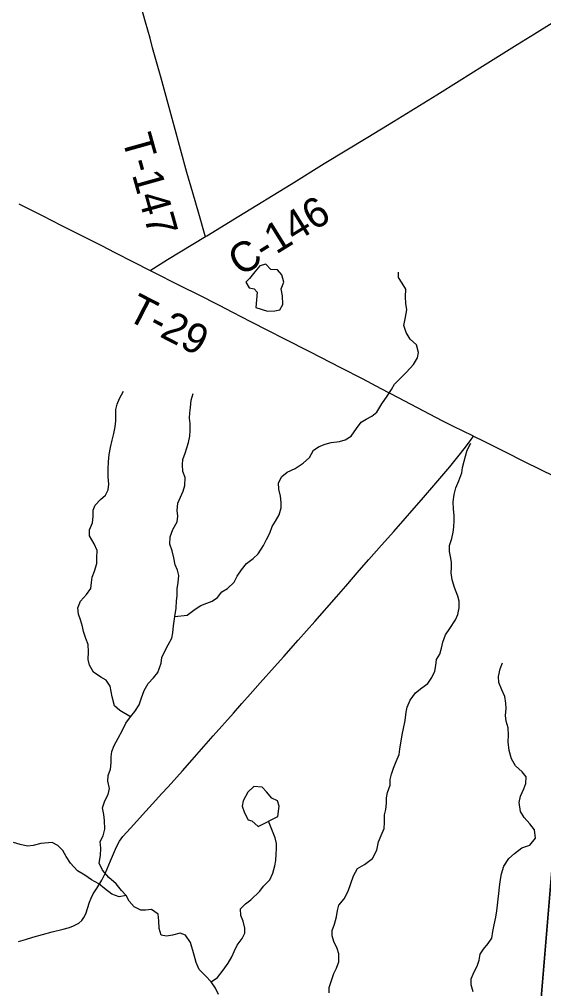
# Model space of a CAD drawing. Extents: x 0 to 1101, y 0 to 440.
# Drawn here: x 846.711 to 847.707, y 379.047 to 380.89 of the extents above; entities that cross this region are included whole.
import ezdxf

# ---------------------------------------------------------------- set-up
doc = ezdxf.new("R2010")
doc.units = 0
for name, color, linetype in [('GM_X_County_Road', 7, 'Continuous'), ('GM_X_County_Road_Text', 7, 'Continuous'), ('GM_X_Minor_Lake', 7, 'Continuous'), ('GM_X_Minor_River', 7, 'Continuous'), ('GM_X_Township_Road', 7, 'Continuous'), ('GM_X_Township_Road_Text', 7, 'Continuous')]:
    doc.layers.add(name, color=color, linetype=linetype)

msp = doc.modelspace()

# ---------------------------------------------------------------- linework, layer by layer
at = {"layer": 'GM_X_County_Road'}
for points in [[(847.5335, 377.0456), (847.6089, 377.9284), (847.6897, 378.8763), (847.7828, 379.9871), (847.8653, 380.9722), (847.896, 381.3391), (846.8323, 381.427), (846.7789, 381.4314), (846.7617, 381.4329), (846.7534, 381.4335), (845.8327, 381.5116), (845.7218, 381.5239), (845.7047, 381.5258), (845.3492, 381.569), (845.0655, 381.6042), (845.008, 381.6114), (844.8229, 381.6343), (844.8107, 381.6358), (844.7738, 381.6404), (844.7118, 381.648), (844.0658, 381.7282)], [(846.9593, 380.4123), (846.9919, 380.4329), (847.0643, 380.4767), (847.0668, 380.4783), (847.1277, 380.5156), (847.2275, 380.5763), (847.2903, 380.6153), (847.3731, 380.6657), (847.4219, 380.6955), (847.5045, 380.7461), (847.5467, 380.7725), (847.5913, 380.8007), (847.6571, 380.842), (847.6898, 380.8623), (847.7238, 380.8828), (847.7671, 380.9084), (847.7921, 380.9236), (847.8525, 380.9605), (847.8635, 380.9676), (847.867, 380.9703), (847.8692, 380.9721)], [(846.7098, 380.5388), (846.7552, 380.5158), (846.7896, 380.4984), (846.8323, 380.4768), (846.8678, 380.459), (846.891, 380.4471), (846.928, 380.428), (846.9593, 380.4123)]]:
    msp.add_lwpolyline(points, dxfattribs=at)
msp.add_lwpolyline([(850.9258, 375.8797), (850.9258, 381.1617), (850.8488, 381.1661), (850.84, 381.1666), (850.8316, 381.167), (850.794, 381.1689), (850.7928, 381.169), (849.9699, 381.2155), (849.9584, 381.2161), (849.5879, 381.237), (848.2076, 381.3203), (847.9626, 381.3347), (847.896, 381.3391), (847.8653, 380.9722), (847.7828, 379.9871), (847.6897, 378.8763), (847.6089, 377.9284), (847.5335, 377.0456), (847.5303, 377.0082), (847.4662, 376.2566), (847.7946, 376.221), (849.0627, 376.0925), (849.9034, 375.9956), (850.1463, 375.9688)], close=True, dxfattribs=at)
at = {"layer": 'GM_X_Minor_Lake'}
for points in [[(847.1601, 380.3417), (847.1824, 380.3349), (847.196, 380.3355), (847.2055, 380.3376), (847.2117, 380.3474), (847.2108, 380.3641), (847.2084, 380.3774), (847.2131, 380.3899), (847.2099, 380.404), (847.2013, 380.4132), (847.1888, 380.4141), (847.1791, 380.4241), (847.1677, 380.4213), (847.158, 380.4096), (847.148, 380.3969), (847.1414, 380.3897), (847.1474, 380.379), (847.1568, 380.3774), (847.1624, 380.3709)], [(847.1624, 380.3709), (847.1601, 380.3417)], [(847.2018, 379.3739), (847.2044, 379.3936), (847.2011, 379.4035), (847.1909, 379.4086), (847.1805, 379.4208), (847.1723, 379.4297), (847.1564, 379.4307), (847.1452, 379.4202), (847.1363, 379.4036), (847.1342, 379.3938), (847.1386, 379.3808), (847.1456, 379.3678), (847.1528, 379.3655), (847.1644, 379.3547)], [(847.1644, 379.3547), (847.2018, 379.3739)]]:
    msp.add_lwpolyline(points, dxfattribs=at)
at = {"layer": 'GM_X_Minor_River'}
for points in [[(847.0063, 379.7542), (847.0295, 379.7569), (847.0448, 379.768), (847.0559, 379.7751), (847.0673, 379.7795), (847.0772, 379.7831), (847.0872, 379.7906), (847.0953, 379.8011), (847.1064, 379.8074), (847.1187, 379.8197), (847.1245, 379.8307), (847.133, 379.8431), (847.1427, 379.8551), (847.1553, 379.8647), (847.1649, 379.8737), (847.1746, 379.8891), (847.1805, 379.9008), (847.1867, 379.9129), (847.191, 379.9253), (847.1976, 379.9355), (847.2046, 379.9475), (847.2086, 379.9608), (847.2084, 379.971), (847.207, 379.9828), (847.2042, 379.9965), (847.2032, 380.0086), (847.2094, 380.0207), (847.2198, 380.0289), (847.235, 380.0355), (847.25, 380.0459), (847.2619, 380.0568), (847.27, 380.0707), (847.2803, 380.0777), (847.2922, 380.0821), (847.3036, 380.085), (847.3191, 380.0871), (847.3298, 380.09), (847.3413, 380.0974), (847.3517, 380.112), (847.3606, 380.1237), (847.3701, 380.1296), (847.3805, 380.1352), (847.39, 380.143), (847.3997, 380.1584), (847.4098, 380.1734), (847.4183, 380.1858), (847.4241, 380.196), (847.4364, 380.2084), (847.4468, 380.2188), (847.4599, 380.2331), (847.4677, 380.2462), (847.4693, 380.2565), (847.4654, 380.2709), (847.4538, 380.2817), (847.446, 380.2944), (847.4416, 380.3073), (847.4445, 380.3236), (847.4473, 380.3372), (847.4456, 380.3494), (847.445, 380.3619), (847.4452, 380.3767), (847.4382, 380.3882), (847.4315, 380.3986), (847.4313, 380.4088)], [(846.9221, 379.5637), (846.9018, 379.5754), (846.8913, 379.5843), (846.8867, 379.6014), (846.8853, 379.6117), (846.8832, 379.6216), (846.8754, 379.6335), (846.8656, 379.6389), (846.8513, 379.6482), (846.8436, 379.6616), (846.8411, 379.6726), (846.842, 379.687), (846.8415, 379.7007), (846.8367, 379.7125), (846.8323, 379.7259), (846.8309, 379.7354), (846.827, 379.7476), (846.8229, 379.7586), (846.8216, 379.7708), (846.8271, 379.7836), (846.8382, 379.796), (846.8464, 379.8076), (846.848, 379.8186), (846.8493, 379.8292), (846.8533, 379.8406), (846.8577, 379.8553), (846.8578, 379.8659), (846.8584, 379.8796), (846.8529, 379.8925), (846.8436, 379.9079), (846.8438, 379.9192), (846.8496, 379.9324), (846.8506, 379.9442), (846.8511, 379.9563), (846.855, 379.9661), (846.8647, 379.9766), (846.8743, 379.9852), (846.8797, 379.995), (846.8806, 380.006), (846.8797, 380.0197), (846.8795, 380.0341), (846.8801, 380.0485), (846.8814, 380.0621), (846.8839, 380.0754), (846.8871, 380.0894), (846.8899, 380.1019), (846.8924, 380.1151), (846.8941, 380.1261), (846.8938, 380.1363), (846.894, 380.1481), (846.8964, 380.1579), (846.9011, 380.1689), (846.9085, 380.1824)], [(847.0135, 379.8322), (847.0114, 379.8425), (847.0066, 379.8528), (847.0045, 379.8661), (847.0013, 379.8791), (846.9969, 379.892), (846.9971, 379.9057), (847.0026, 379.9196), (847.0104, 379.934), (847.0117, 379.9449), (847.0107, 379.956), (847.0116, 379.9696), (847.0167, 379.9813), (847.0222, 379.9926), (847.0254, 380.0036), (847.026, 380.0184), (847.0212, 380.0298), (847.0206, 380.0427), (847.0215, 380.0529), (847.0255, 380.0647), (847.029, 380.0752), (847.0322, 380.0851), (847.0346, 380.0972), (847.0355, 380.107), (847.0354, 380.1211), (847.034, 380.1313), (847.0349, 380.1412), (847.0358, 380.1518), (847.0375, 380.1654), (847.0411, 380.1783)], [(847.5534, 380.0375), (847.5562, 380.0496), (847.559, 380.0594), (847.5618, 380.0704), (847.5689, 380.0839)], [(847.2998, 379.039), (847.2999, 379.0488), (847.3039, 379.0621), (847.3082, 379.0753), (847.3137, 379.0855), (847.3177, 379.0979), (847.3179, 379.1127), (847.315, 379.123), (847.3087, 379.136), (847.3051, 379.147), (847.3056, 379.1573), (847.3096, 379.169), (847.3136, 379.183), (847.3153, 379.1955), (847.3181, 379.2053), (847.3281, 379.2177), (847.3355, 379.232), (847.341, 379.2463), (847.3457, 379.261), (847.3535, 379.275), (847.3669, 379.2824), (847.3818, 379.2939), (847.39, 379.3101), (847.3933, 379.326), (847.3984, 379.3381), (847.4039, 379.3509), (847.4048, 379.3627), (847.4046, 379.3771), (847.4074, 379.3873), (847.4083, 379.3994), (847.4085, 379.4093), (847.4105, 379.4195), (847.4157, 379.4335), (847.4158, 379.4441), (847.4178, 379.4547), (847.4222, 379.4656), (847.4269, 379.4784), (847.4324, 379.492), (847.4341, 379.5022), (847.4382, 379.5295), (847.4411, 379.5416), (847.4443, 379.5564), (847.4457, 379.5723), (847.4481, 379.5821), (847.4536, 379.5949), (847.4636, 379.6088), (847.4759, 379.6185), (847.4874, 379.6271), (847.4951, 379.638), (847.5002, 379.65), (847.5023, 379.661), (847.5039, 379.6724), (847.5101, 379.6829), (847.5133, 379.6943), (847.5158, 379.7052), (847.5205, 379.7192), (847.529, 379.7316), (847.5399, 379.7481), (847.5442, 379.7579), (847.547, 379.7708), (847.5468, 379.7837), (847.5443, 379.7932), (847.5381, 379.8096), (847.5337, 379.8237), (847.5317, 379.837), (847.5322, 379.8469), (847.5323, 379.8575), (847.5306, 379.8682), (847.5284, 379.8781), (847.5286, 379.8894), (847.5326, 379.9023), (847.5354, 379.9144), (847.5367, 379.9242), (847.5372, 379.9368), (847.537, 379.9466), (847.536, 379.9584), (847.5351, 379.9721), (847.5372, 379.9865), (847.5404, 379.9986), (847.5462, 380.0121), (847.5518, 380.0276), (847.5534, 380.0375)], [(847.0894, 379.0355), (847.0835, 379.0474), (847.0753, 379.0596), (847.0645, 379.0711), (847.0522, 379.0831), (847.0466, 379.0961), (847.0427, 379.1102), (847.0362, 379.1341), (847.0265, 379.1483), (847.016, 379.1519), (847.0019, 379.1483), (846.9901, 379.1466), (846.9799, 379.1486), (846.9763, 379.1612), (846.9758, 379.1756), (846.9744, 379.1881), (846.9617, 379.197), (846.9507, 379.1961), (846.9412, 379.1958), (846.9288, 379.2021), (846.9194, 379.2132), (846.9139, 379.2235), (846.905, 379.2335), (846.8945, 379.2458), (846.8807, 379.2578), (846.8687, 379.272), (846.8621, 379.285), (846.8646, 379.3001), (846.8652, 379.3137), (846.8642, 379.3263), (846.8697, 379.3372), (846.8733, 379.3501), (846.8727, 379.3664), (846.871, 379.3778), (846.8689, 379.3903), (846.8733, 379.4036), (846.8795, 379.416), (846.8819, 379.427), (846.8787, 379.441), (846.8792, 379.4517), (846.8836, 379.4637), (846.8853, 379.4759), (846.8854, 379.4876), (846.8863, 379.4978), (846.8907, 379.5088), (846.8984, 379.5227), (846.9066, 379.5382), (846.9133, 379.5517), (846.9221, 379.5637), (846.9299, 379.5735), (846.9384, 379.5863), (846.9427, 379.5999), (846.9479, 379.6135), (846.9556, 379.6266), (846.9656, 379.6375), (846.9737, 379.6476), (846.9804, 379.6654), (846.9817, 379.676), (846.9887, 379.6907), (846.9938, 379.7005), (847.0004, 379.7129), (847.0021, 379.7235), (847.0034, 379.7364), (847.0063, 379.7542), (847.0084, 379.7704), (847.0094, 379.7841), (847.0103, 379.7936), (847.0108, 379.8068), (847.0125, 379.819), (847.0135, 379.8322)], [(847.5731, 379.0408), (847.5695, 379.0541), (847.5696, 379.0655), (847.5751, 379.0783), (847.5813, 379.0893), (847.5849, 379.101), (847.5866, 379.1119), (847.5932, 379.1217), (847.602, 379.1322), (847.609, 379.1427), (847.6107, 379.1552), (847.6135, 379.1681), (847.6164, 379.1825), (847.6184, 379.1946), (847.6194, 379.2052), (847.621, 379.2166), (847.6219, 379.2275), (847.6236, 379.2393), (847.6249, 379.2503), (847.627, 379.2647), (847.6318, 379.2794), (847.6415, 379.2941), (847.6518, 379.3034), (847.666, 379.3142), (847.6809, 379.3197), (847.692, 379.3328), (847.69, 379.3488), (847.6814, 379.3599), (847.6702, 379.3718), (847.6632, 379.3837), (847.6608, 379.4004), (847.6636, 379.4129), (847.6699, 379.4268), (847.6738, 379.437), (847.674, 379.4492), (847.6665, 379.4587), (847.6538, 379.4703), (847.646, 379.4837), (847.6417, 379.4997), (847.6397, 379.5157), (847.6406, 379.5285), (847.6397, 379.5426), (847.6361, 379.5555), (847.6351, 379.5658), (847.6364, 379.5791), (847.6358, 379.5897), (847.6337, 379.6022), (847.6278, 379.6145), (847.6219, 379.6286), (847.6213, 379.64), (847.6246, 379.6547), (847.6289, 379.6664)], [(847.0753, 379.0596), (847.0872, 379.0678), (847.098, 379.0817), (847.1077, 379.0948), (847.1146, 379.1072), (847.119, 379.1174), (847.1248, 379.1295), (847.1341, 379.1419), (847.1392, 379.1524), (847.1393, 379.1619), (847.1361, 379.1748), (847.1317, 379.1855), (847.1311, 379.1981), (847.1403, 379.2078), (847.1507, 379.2156), (847.168, 379.2317), (847.1749, 379.2418), (847.1868, 379.2538), (847.1927, 379.2662), (847.1963, 379.2802), (847.198, 379.2901), (847.1989, 379.3022), (847.1994, 379.3124), (847.1992, 379.3227), (847.1971, 379.3333), (847.1844, 379.3649)], [(846.9139, 379.2235), (846.9006, 379.2211), (846.8863, 379.2262), (846.8724, 379.237), (846.8615, 379.2459), (846.8476, 379.2533), (846.8349, 379.2622), (846.821, 379.2707), (846.8079, 379.2853), (846.7997, 379.2976), (846.7931, 379.3095), (846.7837, 379.3191), (846.7728, 379.3245), (846.7516, 379.3226), (846.7371, 379.319), (846.7261, 379.3176), (846.7121, 379.3205), (846.6993, 379.3248)]]:
    msp.add_lwpolyline(points, dxfattribs=at)
at = {"layer": 'GM_X_Township_Road'}
for points in [[(847.0643, 380.4767), (847.0639, 380.4781), (847.052, 380.5204), (847.0406, 380.5598), (847.0292, 380.5985), (847.0046, 380.6871), (846.98, 380.7777), (846.964, 380.8358), (846.9594, 380.8538), (846.9504, 380.8841), (846.9356, 380.9367)], [(846.9593, 380.4123), (847.0194, 380.3819), (847.0494, 380.367), (847.0904, 380.3462), (847.1157, 380.3329), (847.1499, 380.3152), (847.1838, 380.2981), (847.2137, 380.2831), (847.2624, 380.2583), (847.3224, 380.227), (847.3621, 380.2065), (847.398, 380.188), (847.4308, 380.1704), (847.514, 380.127), (847.5356, 380.116), (847.5718, 380.0984), (847.5738, 380.0974), (847.5936, 380.0877), (847.633, 380.068), (847.6718, 380.0483), (847.7274, 380.0211), (847.754, 380.0075), (847.7873, 379.9908)], [(846.7089, 379.136), (846.7225, 379.1403), (846.736, 379.1448), (846.7545, 379.1498), (846.7731, 379.1546), (846.7939, 379.1597), (846.8057, 379.1631), (846.8132, 379.1663), (846.8183, 379.1684), (846.8239, 379.1714), (846.8291, 379.1761), (846.8332, 379.1818), (846.8368, 379.1891), (846.844, 379.211), (846.8471, 379.219), (846.8512, 379.2271), (846.8582, 379.2381), (846.8672, 379.2531), (846.8741, 379.267), (846.8838, 379.2899), (846.8953, 379.316), (846.901, 379.3269), (846.9072, 379.3359), (846.9216, 379.352), (846.9512, 379.3838), (846.9703, 379.4048), (846.9809, 379.417), (846.9935, 379.4306), (847.021, 379.4611), (847.0389, 379.4817), (847.0616, 379.5071), (847.0793, 379.5271), (847.1175, 379.5705), (847.1334, 379.5887), (847.1492, 379.6063), (847.1686, 379.628), (847.1954, 379.6583), (847.2133, 379.678), (847.2409, 379.7092), (847.2723, 379.7445), (847.3137, 379.7917), (847.3313, 379.8118), (847.3569, 379.8414), (847.3752, 379.8625), (847.399, 379.8896), (847.4224, 379.9161), (847.4788, 379.9808), (847.4985, 380.0032), (847.5288, 380.0386), (847.5445, 380.0578), (847.5591, 380.0764), (847.5695, 380.0909), (847.5738, 380.0974)]]:
    msp.add_lwpolyline(points, dxfattribs=at)

# ---------------------------------------------------------------- texts
at = {"layer": 'GM_X_County_Road_Text'}
msp.add_text('C-146', height=0.05682, rotation=31.8595, dxfattribs=at).set_placement((847.1306, 380.3997))
at = {"layer": 'GM_X_Township_Road_Text'}
for s, rotation, p in [('T-147', 285.5993, (846.9052, 380.6636)), ('T-29', 332.8016, (846.9117, 380.32))]:
    msp.add_text(s, height=0.05682, rotation=rotation, dxfattribs=at).set_placement(p)

doc.saveas('drawing.dxf')
